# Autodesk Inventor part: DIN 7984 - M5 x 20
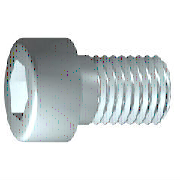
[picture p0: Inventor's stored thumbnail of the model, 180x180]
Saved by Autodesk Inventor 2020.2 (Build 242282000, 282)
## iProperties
Manager: www.cadconsulting.pl
Company: Fabian Stasiak CAD Consulting
Created: 2011-02
Part Number: DIN 7984 - M5 x 20
Material: Stal, miękka
Description: Wkręt z łbem półkolistym walcowym
Document SubType Name: Modeling
Standard: DIN 7984
Designer: F.Stasiak
Standard Revision: 1985
Standards Organization: DIN
Language: pl-PL
Size Designation: M5 x 20
Categories: <MemberInstance><Categories><Category DisplayName="Mocowania" InternalName="e4da775c-781d-43d5-af7c-5136215cf5a6" Mnemonic="FSTN"><Category DisplayName="Śruby"
Density: 1 g/cm^3
Appearance: Metal-Stal
IsCustomPart: 0
Author: F.Stasiak
Subject: Zbiór ćwiczeń. Autodesk Inventor 2020. Kurs podstawowy
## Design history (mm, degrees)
sketch "Szkic1"
  geometry: L1 (0.2, 0)-(20, 0); L2 (20, 0)-(20, 2.5); L3 (20, 2.5)-(2.4, 2.5); L4 (2.4, 2.5)-(1.909, 2.5); L5 (1.909, 2.5)-(0, 2.5); L6 (0, 2.5)-(0, 4.25); L7 (0, 4.25)-(-3.5, 4.25); L8 (-3.5, 4.25)-(-3.5, 1.732); L9 (-3.5, 1.732)-(-0.8, 1.732); L10 (-0.8, 1.732)-(0.2, 0); L11 (-8.2, 0)-(24.7, 0) reference; L12 (0, -0.85)-(0, 5.1) reference; L13 (2.4, 2.5)-(0, 2.5)
  constraints: 22 end point, 6 parallel, 2 collinear, 2 perpendicular, 1 horizontal, 1 point on line
  dimensions: "d1" = 17.6 distance from line of L3.end L2 (= GEL); "d2" = 0.49086 distance of L4.end L3.end (computed from GAL); "d3" = 3.5 distance between parallel lines of L8 L6 (= KOH); "d4" = 2.7 distance of L8.end L9.end (= INTI); "d5" = 60 deg angle of L10 L1; "d6" = 5 diameter of L3 L1 (= GD); "d7" = 5 diameter of L5 L1 (= BDM); "d8" = 3.4641 diameter of L9 L1 (= 1.1547 x SW); "d9" = 8.5 diameter of L7 L1 (= KOD); "d26" = 20 distance between parallel lines of L12 L2 (= NLG)
revolve "Bryła" sketch "Szkic1" stored, may be unused: angle "d10" = 90 deg
sketch "Szkic2"
  geometry: L1 (0, -5.95)-(0, 5.95) reference; L2 (-5.95, 0)-(5.95, 0) reference; L3 (1.732, 0)-(0.866, -1.5); L4 (0.866, -1.5)-(-0.866, -1.5); L5 (-0.866, -1.5)-(-1.732, 0); L6 (-1.732, 0)-(-0.866, 1.5); L7 (-0.866, 1.5)-(0.866, 1.5); L8 (0.866, 1.5)-(1.732, 0); 2 further points
  constraints: 12 end point, 1 coincident, 1 horizontal alignment, 1 point on line, 12 other
extrude "Szczelina" join sketch "Szkic2" stored distance "d11" = 10; taper "d12" = 0 deg
workplane "Work Plane1"
fillet "Fillet2" dims "d30" = 0.1 (= R)
body "Solid1"
fillet "Zaokrąglenie1" dims "d17" = 0.5 (= RR)
feature "Gwint" dims "d13" = 17.6 (= GEL), "d14" = 0
chamfer "Faza1" distance "d15" = 0.49076 (= -0.5 x SPD + 0.5 x GD); stored, may be unused: second distance "d16" = 0.49076 (= GUL), angle "d27" = 45 deg
other parameters: "GD" = 5 (= NND) [user parameter; used in 2 equation terms], "NLG" = 20 [user parameter; used in 1 equation term], "GEL" = 17.6 [user parameter; used in 2 equation terms], "KOD" = 8.5 [user parameter; used in 1 equation term], "KOH" = 3.5 [user parameter; used in 1 equation term], "INTI" = 2.7 [user parameter; used in 1 equation term], "GAL" = 0.49076 (= 0.61345 x PTC) [user parameter; used in 1 equation term], "GUL" = 0.49076 (= 0.61345 x PTC) [user parameter; used in 1 equation term], "BDM" = 5 (= NND) [user parameter; used in 1 equation term], "SW" = 3 [user parameter; used in 2 equation terms], "RR" = 0.5 [user parameter; used in 1 equation term], "SPD" = 4.01848 (= NND - 1.2269 x PTC) [user parameter; used in 1 equation term], "d19" = 0, "d28" = 0, "d29" = 0, "R" = 0.1 [user parameter; used in 1 equation term], "TOA" = 30 deg [user parameter], "GD1" = 4.01848 (= THREADDIA - 1.2269 x PTC) [user parameter], "THREADDIA" = 5 [user parameter; used in 1 equation term], "FAWI" = 45 deg [user parameter], "ANG" = 120 deg [user parameter], "TPU" = 12.5 (computed from PTC) [user parameter], "PTC" = 0.8 [user parameter; used in 5 equation terms], "NND" = 5 [user parameter; used in 3 equation terms], "E0" = 3.465 (= 1.155 x SW) [user parameter]
